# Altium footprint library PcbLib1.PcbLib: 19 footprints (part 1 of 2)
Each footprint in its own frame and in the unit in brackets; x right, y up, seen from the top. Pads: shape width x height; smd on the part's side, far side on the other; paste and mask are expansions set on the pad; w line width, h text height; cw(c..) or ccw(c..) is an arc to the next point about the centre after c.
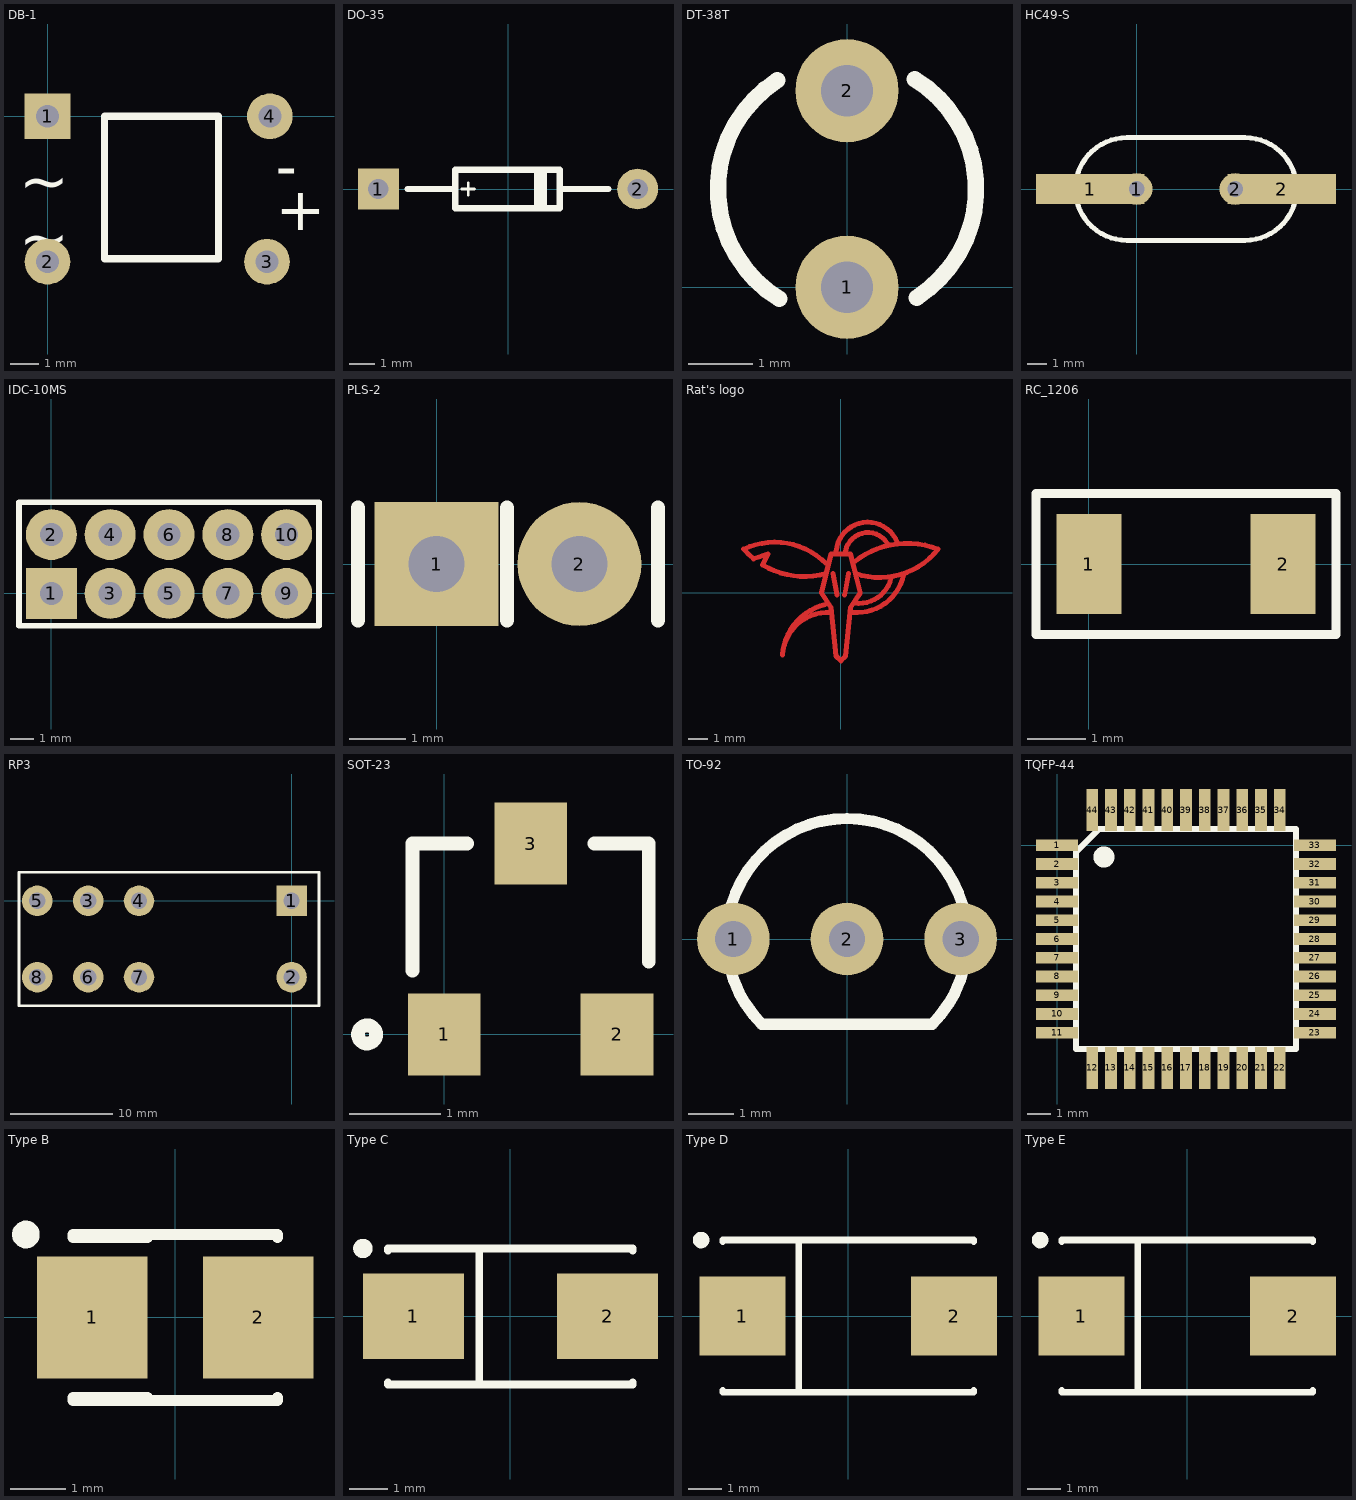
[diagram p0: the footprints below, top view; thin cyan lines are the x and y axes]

## DB-1 [mm]
height 5
pads (4):
  rect 1.6x1.6 hole 0.8: 1(0,0)
  round 1.6 hole 0.8: 2(0,-5.1) 3(7.7,-5.1) 4(7.8,0)
Top Overlay:
  lines w0.254: 2,-5 2,0 6,0 6,-5 2,-5
  text "~" at -1,-3 h1.52
  text "~" at -1,-5 h1.52
  text "+" at 8,-4 h1.52
  text "-" at 8,-2.5 h1.52
3D body: height 4.75, standoff -2.65, extent -0.1,-6.81 7.9,1.7

## DO-35 [mm]
height 2
pads (2):
  rect 1.6x1.6 hole 0.8: 1(-5.084,0)
  round 1.6 hole 0.8: 2(5.084,0)
Top Overlay:
  region: 1.024,-0.75 1.524,-0.75 1.524,0.75 1.024,0.75
  lines w0.1: -1.813,0 -1.314,0 ; -1.563,-0.25 -1.563,0.25
  lines w0.25: -3.937,0 -2.064,0 ; 2.044,0 3.937,0 ; -2.064,-0.75 2.032,-0.75 2.032,0.75 -2.064,0.75 -2.064,-0.75
3D body: height 2.15, standoff -2.54, extent -5.35,-0.889 5.343,0.864

## DT-38T [mm]
height 8.9
pads (2):
  round 1.6 hole 0.8: 1(0,0) 2(0,3.048)
Top Overlay:
  lines w0.254: -1.082,3.207 ccw(c0,1.524) -1.048,-0.179 ; 1.048,3.227 cw(c0,1.524) 1.082,-0.158
3D body: height 9.77, standoff -1, extent -1.6,-0.199 1.6,3.248

## HC49-S [mm]
height 4
pads (4):
  rect 5.5x1.5 smd: 1(-2.35,0) 2(7.35,0)
  round 1.6 hole 0.8: 1(0,0) 2(5,0)
Top Overlay:
  lines w0.25: -0.5,-2.6 cw(c-0.5,0) -0.5,2.6 5.5,2.6 cw(c5.5,0) 5.5,-2.6 -0.5,-2.6
Bottom Overlay:
  lines w0.25: -0.5,-2.6 cw(c-0.5,0) -0.5,2.6 5.5,2.6 cw(c5.5,0) 5.5,-2.6 -0.5,-2.6
3D body: height 1.9, standoff -13.3, extent -2.96,-2.286 8.04,2.214

## IDC-10MS [mm]
height 5
pads (10):
  rect 2.2x2.2 hole 1: 1(0,0)
  round 2.2 hole 1: 2(0,2.54) 3(2.54,0) 4(2.54,2.54) 5(5.08,0) 6(5.08,2.54) 7(7.62,0) 8(7.62,2.54) 9(10.16,0) 10(10.16,2.54)
Top Overlay:
  lines w0.254: -1.397,-1.397 11.557,-1.397 11.557,3.937 -1.397,3.937 -1.397,-1.397
3D body: height 8.54, standoff -2.96, extent -1.27,-1.27 11.43,3.81

## PLS-2 [mm]
height 5
pads (2):
  rect 2.2x2.2 hole 1: 1(0,0)
  round 2.2 hole 1: 2(2.54,0)
Top Overlay:
  lines w0.25: -1.397,-1 -1.397,1 ; 1.25,-1 1.25,1 ; 3.937,-1 3.937,1
3D body: height 8.54, standoff -3, extent -1.27,-1.27 3.81,1.27

## Rat's logo [mm]
Top Layer:
  lines w0.254: -4.516,1.786 cw(c-1.875,5.025) -5,2.25 cw(c-3.402,-1.109) -0.75,1.5 ; -4.5,1.75 -3.75,2 -4,1.5 ; -4.033,1.446 ccw(c-1.875,5.025) -0.75,1 ; -0.8,-0.6 ccw(c-0.153,-3.378) -3,-3.2 cw(c-0.65,-3.35) -0.5,-1 ; -0.4,1 -0.2,-0.1 ; -0.238,2.147 cw(c1.384,2.012) 2.9,2.6 ; 0.2,-0.1 0.4,1 ; 0.239,2.148 cw(c1.394,1.929) 2.395,2.546 ; 0.6,-1 ccw(c0.831,1.445) 3.23,0.923 ; 0.652,1.562 cw(c3.411,-1.797) 5,2.25 cw(c2,4.6) 0.75,1 ; 0.711,-0.52 ccw(c0.937,1.169) 2.6,0.8 ; -1,0 -0.5,-0.75 -0.25,-3.25 0,-3.5 0.25,-3.25 0.5,-0.75 1,0 0.5,2 -0.5,2 -1,0

## RC_1206 [mm]
height 1.5
pads (2):
  rect 1.1x1.7 smd: 1(0,0) 2(3.3,0)
Top Overlay:
  lines w0.15: -0.9,-1.2 -0.9,1.2 4.2,1.2 4.2,-1.2 -0.9,-1.2
3D body: height 1, standoff 0, extent 0.05,-0.8 3.25,0.8

## RP3 [mm]
height 16
pads (8):
  rect 3x3 hole 1.6: 1(0,0)
  round 3 hole 1.6: 2(0,-7.5) 3(-20,0) 4(-15,0) 5(-25,0) 6(-20,-7.5) 7(-15,-7.5) 8(-25,-7.5)
Top Overlay:
  lines w0.25: -26.8,-10.3 2.7,-10.3 2.7,2.8 -26.8,2.8 -26.8,-10.3
3D body: height 15.7, standoff -3.9, extent -26.5,-10.1 2.5,2.6

## SOT-23 [mm]
height 1.2
pads (3):
  rect 0.8x0.9 smd: 1(0,0) 2(1.9,0) 3(0.95,2.1)
Top Overlay:
  circle w0.15: c-0.85,0 r0.1
  lines w0.15: -0.35,0.7 -0.35,2.1 0.25,2.1 ; 1.65,2.1 2.25,2.1 2.25,0.8
3D body: height 1.05, standoff -0.05, extent -0.55,-0.2 2.45,2.3

## TO-92 [mm]
height 5
pads (3):
  round 1.6 hole 0.8: 1(-2.5,0) 2(0,0) 3(2.5,0)
Top Overlay:
  lines w0.25: -1.875,-1.875 cw(c0,0) 1.875,-1.875 -1.875,-1.875
3D body: height 9.7, standoff -2.7, extent -2.798,-1.746 2.798,2.184

## TQFP-44 [mm]
height 1.2
pads (44):
  rect 1.8x0.5 smd: 1(0,0) 2(0,-0.8) 3(0,-1.6) 4(0,-2.4) 5(0,-3.2) 6(0,-4) 7(0,-4.8) 8(0,-5.6) 9(0,-6.4) 10(0,-7.2) 11(0,-8) 23(11,-8) 24(11,-7.2) 25(11,-6.4) 26(11,-5.6) 27(11,-4.8) 28(11,-4) 29(11,-3.2) 30(11,-2.4) 31(11,-1.6) 32(11,-0.8) 33(11,0)
  rect 0.5x1.8 smd: 12(1.5,-9.5) 13(2.3,-9.5) 14(3.1,-9.5) 15(3.9,-9.5) 16(4.7,-9.5) 17(5.5,-9.5) 18(6.3,-9.5) 19(7.1,-9.5) 20(7.9,-9.5) 21(8.7,-9.5) 22(9.5,-9.5) 34(9.5,1.5) 35(8.7,1.5) 36(7.9,1.5) 37(7.1,1.5) 38(6.3,1.5) 39(5.5,1.5) 40(4.7,1.5) 41(3.9,1.5) 42(3.1,1.5) 43(2.3,1.5) 44(1.5,1.5)
Top Overlay:
  circle w0.5: c2,-0.5 r0.2
  lines w0.25: 0.8,-8.7 0.8,-0.3 1.8,0.7 10.2,0.7 10.2,-8.7 0.8,-8.7
3D body: height 1.1, standoff 0, extent -0.539,-9.968 11.461,2.032

## Type B [mm]
height 2.5
pads (2):
  rect 2x2.2 smd: 1(-1.5,0) 2(1.5,0)
Top Overlay:
  circle w0.25: c-2.7,1.5 r0.125
  lines w0.2: -1.85,-1.5 1.85,-1.5 1.85,-1.45 ; -1.85,-1.45 -0.5,-1.45 ; -1.85,1.45 -0.5,1.45 ; -1.85,1.5 1.85,1.5 1.85,1.45
3D body: height 1.89, standoff -0.02, extent -1.831,-1.4 1.832,1.4

## Type C [mm]
height 3.4
pads (2):
  rect 2.6x2.2 smd: 1(-2.5,0) 2(2.5,0)
Top Overlay:
  circle w0.25: c-3.8,1.75 r0.125
  lines w0.2: -3.15,-1.7 -3.15,-1.75 3.15,-1.75 3.15,-1.7 ; -3.15,1.7 -3.15,1.75 3.15,1.75 3.15,1.7 ; -0.8,-1.75 -0.8,1.75
3D body: height 2.79, standoff -0.04, extent -3.799,-1.8 3.799,1.713

## Type D [mm]
height 3.7
pads (2):
  rect 2.6x2.4 smd: 1(-3.2,0) 2(3.2,0)
Top Overlay:
  circle w0.25: c-4.45,2.3 r0.125
  lines w0.2: -3.8,-2.25 -3.8,-2.3 3.8,-2.3 3.8,-2.25 ; -3.8,2.25 -3.8,2.3 3.8,2.3 3.8,2.25 ; -1.5,-2.3 -1.5,2.3
3D body: height 3, standoff 0, extent -3.7,-2.225 3.7,2.225

## Type E [mm]
height 4.1
pads (2):
  rect 2.6x2.4 smd: 1(-3.2,0) 2(3.2,0)
Top Overlay:
  circle w0.25: c-4.45,2.3 r0.125
  lines w0.2: -3.8,-2.25 -3.8,-2.3 3.8,-2.3 3.8,-2.25 ; -3.8,2.25 -3.8,2.3 3.8,2.3 3.8,2.25 ; -1.5,-2.3 -1.5,2.3
3D body: height 4.1, standoff 0, extent -3.76,-2.255 3.76,2.255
